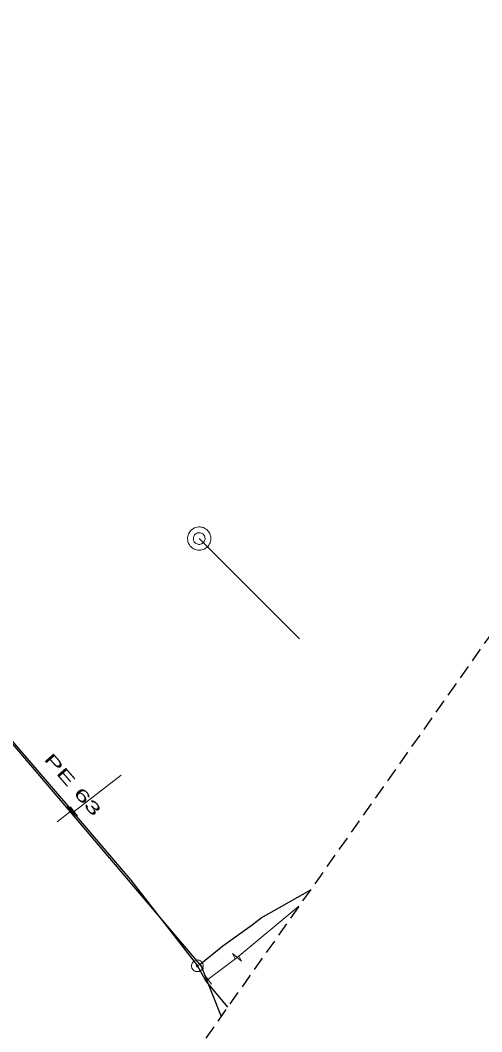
# Model space of a CAD drawing. Extents: x -779496 to -779026, y -977086 to -976624.
# Drawn here: x -779153.6 to -779114, y -976850.3 to -976763.6 of the extents above; entities that cross this region are included whole.
import ezdxf

# ---------------------------------------------------------------- set-up
doc = ezdxf.new("R2010")
doc.units = 0
doc.header["$LTSCALE"] = 0.4
doc.linetypes.add('MEDIUM_DASHED', pattern=[4.5, 3, -1.5])
for name, color, linetype, lineweight in [('1', 7, 'MEDIUM_DASHED', 25), ('11', 7, 'Continuous', 13), ('13', 7, 'Continuous', 13), ('14', 7, 'Continuous', 13), ('17', 7, 'Continuous', 25), ('22', 7, 'Continuous', 13), ('34', 7, 'Continuous', 13), ('47', 7, 'Continuous', 13)]:
    doc.layers.add(name, color=color, linetype=linetype, lineweight=lineweight)

msp = doc.modelspace()

# ---------------------------------------------------------------- linework, layer by layer
at = {"layer": '1'}
msp.add_lwpolyline([(-779144.045, -976624.23), (-779025.876, -976692.559), (-779211.57, -976955.425), (-779456.75, -977086.455), (-779496.14, -976963.463), (-779320.896, -976797.866)], close=True, dxfattribs=at)
at = {"layer": '11'}
msp.add_line((-779129.652, -976816.633), (-779138.25, -976808.035), dxfattribs=at)
at = {"layer": '13'}
for p, q in [((-779148.986, -976831.416), (-779144.949, -976828.317)), ((-779149.265, -976831.386), (-779150.421, -976832.304)), ((-779149.191, -976831.304), (-779149.265, -976831.386)), ((-779149.079, -976831.467), (-779148.986, -976831.416)), ((-779135.001, -976843.918), (-779129.704, -976839.537)), ((-779137.504, -976845.825), (-779135.001, -976843.918)), ((-779137.66, -976845.975), (-779137.504, -976845.825))]:
    msp.add_line(p, q, dxfattribs=at)
at = {"layer": '14'}
msp.add_line((-779138.208, -976844.52), (-779138.408, -976844.644), dxfattribs=at)
at = {"layer": '17'}
msp.add_line((-779138.088, -976844.662), (-779136.369, -976848.972), dxfattribs=at)
for points in [[(-779187.682, -976792.625), (-779186.592, -976793.16), (-779179.717, -976795.781), (-779149.307, -976831.449), (-779138.088, -976844.662)], [(-779186.629, -976792.713), (-779186.179, -976792.991), (-779182.515, -976794.103), (-779178.658, -976796.833), (-779172.333, -976804.278), (-779165.603, -976812.539), (-779157.438, -976821.754), (-779149.191, -976831.304), (-779149.079, -976831.467), (-779144.1, -976837.296), (-779138.408, -976844.644)], [(-779138.208, -976844.52), (-779136.219, -976842.92), (-779133.699, -976841.14), (-779132.93, -976840.539), (-779128.73, -976838.158)], [(-779138.408, -976844.644), (-779138.395, -976844.663), (-779137.66, -976845.975), (-779135.822, -976848.197)]]:
    msp.add_lwpolyline(points, dxfattribs=at)
at = {"layer": '22'}
for points in [[(-779137.25, -976808.035), (-779137.256, -976807.926), (-779137.274, -976807.818), (-779137.304, -976807.712), (-779137.344, -976807.611), (-779137.396, -976807.514), (-779137.458, -976807.424), (-779137.53, -976807.341), (-779137.61, -976807.267), (-779137.698, -976807.201), (-779137.792, -976807.146), (-779137.892, -976807.101), (-779137.997, -976807.068), (-779138.104, -976807.046), (-779138.213, -976807.036), (-779138.323, -976807.038), (-779138.431, -976807.052), (-779138.538, -976807.077), (-779138.641, -976807.114), (-779138.739, -976807.163), (-779138.831, -976807.221), (-779138.917, -976807.29), (-779138.994, -976807.367), (-779139.063, -976807.453), (-779139.122, -976807.545), (-779139.17, -976807.643), (-779139.207, -976807.746), (-779139.233, -976807.853), (-779139.247, -976807.961), (-779139.249, -976808.071), (-779139.239, -976808.18), (-779139.218, -976808.287), (-779139.184, -976808.391), (-779139.14, -976808.491), (-779139.085, -976808.586), (-779139.019, -976808.674), (-779138.945, -976808.754), (-779138.862, -976808.826), (-779138.772, -976808.888), (-779138.676, -976808.94), (-779138.574, -976808.981), (-779138.469, -976809.011), (-779138.361, -976809.029), (-779138.251, -976809.035), (-779138.142, -976809.029), (-779138.034, -976809.011), (-779137.929, -976808.982), (-779137.827, -976808.941), (-779137.73, -976808.889), (-779137.64, -976808.827), (-779137.557, -976808.756), (-779137.482, -976808.676), (-779137.417, -976808.588), (-779137.361, -976808.494), (-779137.317, -976808.394), (-779137.283, -976808.29), (-779137.261, -976808.182), (-779137.251, -976808.073)], [(-779137.75, -976808.035), (-779137.756, -976807.958), (-779137.774, -976807.883), (-779137.803, -976807.811), (-779137.843, -976807.745), (-779137.893, -976807.685), (-779137.951, -976807.634), (-779138.016, -976807.593), (-779138.087, -976807.562), (-779138.162, -976807.543), (-779138.239, -976807.535), (-779138.317, -976807.539), (-779138.392, -976807.556), (-779138.465, -976807.583), (-779138.532, -976807.622), (-779138.592, -976807.67), (-779138.644, -976807.728), (-779138.687, -976807.792), (-779138.719, -976807.862), (-779138.74, -976807.937), (-779138.75, -976808.014), (-779138.747, -976808.091), (-779138.732, -976808.167), (-779138.706, -976808.24), (-779138.669, -976808.308), (-779138.622, -976808.369), (-779138.566, -976808.423), (-779138.502, -976808.467), (-779138.432, -976808.501), (-779138.358, -976808.523), (-779138.282, -976808.534), (-779138.204, -976808.533), (-779138.128, -976808.52), (-779138.055, -976808.495), (-779137.986, -976808.46), (-779137.924, -976808.414), (-779137.869, -976808.359), (-779137.824, -976808.296), (-779137.788, -976808.227), (-779137.764, -976808.154), (-779137.752, -976808.077)]]:
    msp.add_lwpolyline(points, close=True, dxfattribs=at)
at = {"layer": '34'}
for p, q in [((-779149.576, -976830.994), (-779148.954, -976831.777)), ((-779149.29, -976831.019), (-779148.681, -976831.812)), ((-779138.521, -976844.13), (-779137.894, -976844.909)), ((-779137.807, -976845.427), (-779137.201, -976846.222))]:
    msp.add_line(p, q, dxfattribs=at)
at = {"layer": '47'}
msp.add_line((-779135.382, -976843.579), (-779135.16, -976844.039), dxfattribs=at)
msp.add_lwpolyline([(-779135.382, -976843.579), (-779134.619, -976844.256), (-779134.841, -976843.796)], dxfattribs=at)
for points in [[(-779138.124, -976845.055), (-779138.083, -976845.023), (-779138.044, -976844.987), (-779138.011, -976844.947), (-779137.981, -976844.905), (-779137.956, -976844.858), (-779137.936, -976844.809), (-779137.922, -976844.759), (-779137.912, -976844.708), (-779137.908, -976844.656), (-779137.909, -976844.604), (-779137.916, -976844.551), (-779137.929, -976844.501), (-779137.946, -976844.452), (-779137.969, -976844.404), (-779137.996, -976844.36), (-779138.028, -976844.319), (-779138.064, -976844.28), (-779138.104, -976844.246), (-779138.146, -976844.217), (-779138.193, -976844.192), (-779138.242, -976844.172), (-779138.292, -976844.157), (-779138.344, -976844.148), (-779138.395, -976844.143), (-779138.447, -976844.145), (-779138.5, -976844.152), (-779138.551, -976844.164), (-779138.599, -976844.182), (-779138.647, -976844.205), (-779138.691, -976844.232), (-779138.732, -976844.264), (-779138.771, -976844.3), (-779138.805, -976844.34), (-779138.834, -976844.382), (-779138.859, -976844.429), (-779138.879, -976844.477), (-779138.894, -976844.527), (-779138.904, -976844.579), (-779138.908, -976844.631), (-779138.906, -976844.683), (-779138.899, -976844.736), (-779138.887, -976844.786), (-779138.869, -976844.835), (-779138.846, -976844.883), (-779138.819, -976844.927), (-779138.787, -976844.968), (-779138.751, -976845.007), (-779138.712, -976845.04), (-779138.669, -976845.07), (-779138.622, -976845.095), (-779138.574, -976845.115), (-779138.524, -976845.13), (-779138.473, -976845.139), (-779138.42, -976845.143), (-779138.368, -976845.142), (-779138.315, -976845.135), (-779138.266, -976845.123), (-779138.216, -976845.105), (-779138.168, -976845.082)], [(-779138.361, -976844.711), (-779138.354, -976844.706), (-779138.348, -976844.7), (-779138.343, -976844.694), (-779138.338, -976844.687), (-779138.333, -976844.679), (-779138.331, -976844.671), (-779138.328, -976844.663), (-779138.326, -976844.654), (-779138.326, -976844.646), (-779138.326, -976844.637), (-779138.327, -976844.628), (-779138.329, -976844.62), (-779138.332, -976844.612), (-779138.335, -976844.604), (-779138.34, -976844.597), (-779138.345, -976844.59), (-779138.351, -976844.584), (-779138.357, -976844.579), (-779138.364, -976844.574), (-779138.372, -976844.569), (-779138.38, -976844.567), (-779138.388, -976844.564), (-779138.397, -976844.562), (-779138.406, -976844.561), (-779138.414, -976844.562), (-779138.423, -976844.563), (-779138.431, -976844.565), (-779138.439, -976844.568), (-779138.447, -976844.571), (-779138.454, -976844.576), (-779138.461, -976844.581), (-779138.467, -976844.587), (-779138.472, -976844.593), (-779138.477, -976844.6), (-779138.482, -976844.608), (-779138.485, -976844.616), (-779138.487, -976844.624), (-779138.489, -976844.633), (-779138.49, -976844.642), (-779138.489, -976844.65), (-779138.488, -976844.659), (-779138.486, -976844.667), (-779138.483, -976844.675), (-779138.48, -976844.683), (-779138.475, -976844.69), (-779138.47, -976844.697), (-779138.464, -976844.703), (-779138.458, -976844.708), (-779138.451, -976844.713), (-779138.443, -976844.718), (-779138.435, -976844.721), (-779138.427, -976844.723), (-779138.418, -976844.725), (-779138.41, -976844.725), (-779138.401, -976844.725), (-779138.392, -976844.724), (-779138.384, -976844.722), (-779138.376, -976844.719), (-779138.368, -976844.716)]]:
    msp.add_lwpolyline(points, close=True, dxfattribs=at)

# ---------------------------------------------------------------- texts
at = {"layer": '1', "width": 1.8}
msp.add_text('PE 63 ', height=1, rotation=311, dxfattribs=at).set_placement((-779151.619, -976826.96))

doc.saveas('drawing.dxf')
